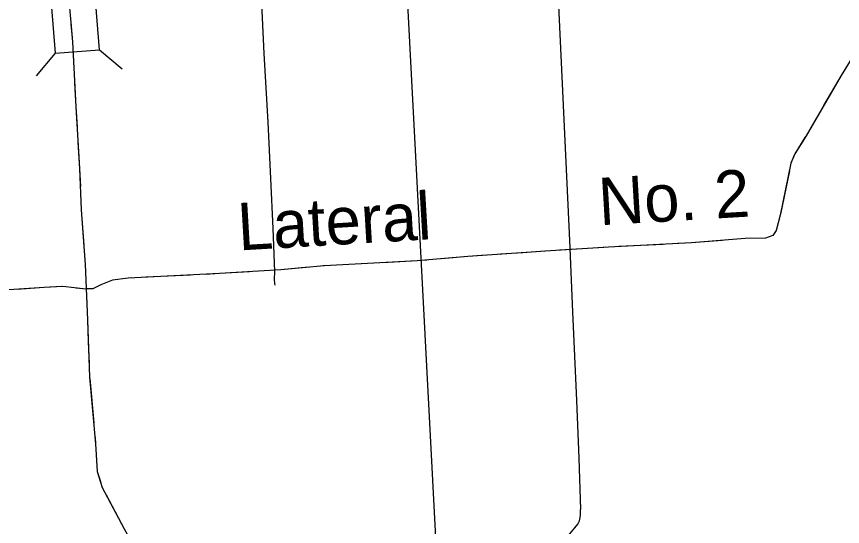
# Model space of a CAD drawing. Extents: x 646058 to 725608, y 1473014 to 1561048.
# Drawn here: x 658973 to 662655, y 1548182 to 1550456 of the extents above; entities that cross this region are included whole.
import ezdxf

# ---------------------------------------------------------------- set-up
doc = ezdxf.new("R2010")
doc.units = 0
doc.layers.add('Default', color=7, linetype='Continuous')

msp = doc.modelspace()

# ---------------------------------------------------------------- linework, layer by layer
at = {"layer": 'Default'}
for p, q in [((659145.5, 1550292.4), (659059.9, 1550191.9)), ((659342.9, 1550308.2), (659443.4, 1550222.6))]:
    msp.add_line(p, q, dxfattribs=at)
msp.add_lwpolyline([(659098, 1550884.5), (659145.5, 1550292.4), (659342.9, 1550308.2), (659295.3, 1550900.3)], close=True, dxfattribs=at)
for points in [[(661378.3, 1550729.1), (661438.2, 1549458.3), (661451.6, 1549139.8), (661469.1, 1548744.2), (661480.1, 1548487), (661487.9, 1548258.1)], [(661378.3, 1550729.1), (661438.2, 1549458.3), (661451.6, 1549139.8), (661469.1, 1548744.2), (661480.1, 1548487), (661487.9, 1548258.1)], [(660846.4, 1548048), (660709.3, 1550682.8)], [(660059.7, 1550642.5), (660076, 1550291.9), (660093.1, 1549984.6)], [(660059.7, 1550642.5), (660076, 1550291.9), (660093.1, 1549984.6)], [(659205.3, 1550547.4), (659215.1, 1550429.5), (659222.5, 1550343.5), (659237.2, 1550053.7), (659254.4, 1549778.6), (659261.8, 1549594.3), (659279, 1549351.2), (659288.8, 1549103.1), (659298.6, 1548847.6), (659325.6, 1548550.4), (659333, 1548427.6), (659355.1, 1548356.4), (659453.3, 1548172.1)], [(659205.3, 1550547.4), (659215.1, 1550429.5), (659222.5, 1550343.5)], [(659215.6, 1550423.5), (659222.5, 1550343.5), (659228.5, 1550225.9)], [(659222.5, 1550343.5), (659237.2, 1550053.7), (659254.4, 1549778.6), (659261.8, 1549594.3), (659279, 1549351.2), (659288.8, 1549103.1), (659298.6, 1548847.6), (659325.6, 1548550.4), (659333, 1548427.6), (659355.1, 1548356.4), (659453.3, 1548172.1)], [(662705.2, 1550284.8), (662649.8, 1550194), (662493, 1549924.9), (662442.3, 1549843.4), (662425.3, 1549801.9), (662377.7, 1549571.3), (662359.2, 1549502.1), (662345.4, 1549480.5), (662311.6, 1549468.2), (662220.9, 1549466.7), (661982.6, 1549446.7), (661612.1, 1549428.2), (661495.2, 1549420.6), (661353.8, 1549411.3), (660984.8, 1549386.7), (660758.8, 1549366.7), (660345.2, 1549345.2), (660151.5, 1549326.8), (659877.9, 1549309.8), (659470.4, 1549289.9), (659401.3, 1549280.6), (659349, 1549260.6), (659313.6, 1549242.2), (659283.3, 1549241.7)], [(662705.2, 1550284.8), (662649.8, 1550194), (662493, 1549924.9), (662442.3, 1549843.4), (662425.3, 1549801.9), (662377.7, 1549571.3), (662359.2, 1549502.1), (662345.4, 1549480.5), (662311.6, 1549468.2), (662220.9, 1549466.7), (661982.6, 1549446.7), (661612.1, 1549428.2), (661495.2, 1549420.6), (661353.8, 1549411.3), (660984.8, 1549386.7), (660758.8, 1549366.7), (660345.2, 1549345.2), (660151.5, 1549326.8), (659877.9, 1549309.8), (659470.4, 1549289.9), (659401.3, 1549280.6), (659349, 1549260.6), (659313.6, 1549242.2), (659283.3, 1549241.7)], [(662671.5, 1550229.7), (662649.8, 1550194), (662571.1, 1550059)], [(659231.8, 1550160), (659237.2, 1550053.7), (659242.9, 1549962.3)], [(660093.1, 1549984.6), (660105.9, 1549734.1), (660115.8, 1549511.8), (660122.6, 1549319.8), (660121.9, 1549283.7), (660122.7, 1549265.3), (660125.1, 1549258)], [(660093.1, 1549984.6), (660105.9, 1549734.1), (660106, 1549730.7)], [(662537.9, 1550002), (662493, 1549924.9), (662487.8, 1549916.6)], [(662487.8, 1549916.6), (662442.3, 1549843.4), (662437.4, 1549831.6)], [(659247, 1549896.5), (659254.4, 1549778.6), (659257.6, 1549698.8)], [(662418.5, 1549768.6), (662378.4, 1549574.7)], [(659260.2, 1549632.8), (659261.8, 1549594.3), (659273, 1549435.3)], [(662361.6, 1549510.9), (662359.2, 1549502.1), (662345.4, 1549480.5), (662311.6, 1549468.2), (662220.9, 1549466.7), (662184.5, 1549463.6)], [(661855.3, 1549440.4), (661657.6, 1549430.5)], [(662118.7, 1549458.1), (661982.6, 1549446.7), (661921.2, 1549443.6)], [(661064.8, 1549392.1), (660984.8, 1549386.7), (660867.5, 1549376.3)], [(661229.5, 1549403), (661130.7, 1549396.5)], [(661328.2, 1549409.6), (661229.5, 1549403)], [(661591.7, 1549426.9), (661495.2, 1549420.6), (661394.1, 1549414)], [(659277.7, 1549369.4), (659279, 1549351.2), (659286.1, 1549171.6)], [(660538.2, 1549355.3), (660345.2, 1549345.2), (660340.5, 1549344.8)], [(660801.7, 1549370.5), (660758.8, 1549366.7), (660604.1, 1549358.7)], [(660011.6, 1549318.1), (659877.9, 1549309.8), (659813.9, 1549306.7)], [(660274.8, 1549338.5), (660151.5, 1549326.8), (660077.5, 1549322.2)], [(659484.3, 1549290.5), (659470.4, 1549289.9), (659401.3, 1549280.6), (659349, 1549260.6), (659313.6, 1549242.2), (659295.2, 1549241.9)], [(659649.1, 1549298.6), (659550.2, 1549293.8)], [(659748, 1549303.5), (659649.1, 1549298.6)], [(658891.1, 1549235.4), (659096.2, 1549249.3), (659180.1, 1549253.8), (659283.3, 1549241.7)], [(658891.1, 1549235.4), (659096.2, 1549249.3), (659180.1, 1549253.8), (659283.3, 1549241.7)], [(658975.6, 1549241.2), (659096.2, 1549249.3), (659173.2, 1549253.4)], [(659238.8, 1549246.9), (659283.3, 1549241.7)], [(659288.7, 1549105.7), (659288.8, 1549103.1), (659292.5, 1549006.7)], [(659292.5, 1549006.7), (659296.3, 1548907.8)], [(659299.1, 1548841.9), (659317.1, 1548644.7)], [(659323, 1548579), (659325.6, 1548550.4), (659333, 1548427.6), (659346.7, 1548383.4)], [(659372.9, 1548323.1), (659453.3, 1548172.1), (659466, 1548148.4)], [(661399.3, 1548081), (661412.6, 1548113.4), (661431.7, 1548140), (661462.4, 1548175.7), (661475.7, 1548192.3), (661483.2, 1548208.1), (661487.4, 1548231.4), (661487.9, 1548258.1)], [(661399.3, 1548081), (661412.6, 1548113.4), (661431.7, 1548140), (661462.4, 1548175.7), (661475.7, 1548192.3), (661483.2, 1548208.1), (661487.4, 1548231.4), (661487.9, 1548258.1)]]:
    msp.add_lwpolyline(points, dxfattribs=at)

# ---------------------------------------------------------------- texts
for s, p in [('No. 2', (661573, 1549525.2)), ('Lateral', (659964.4, 1549413))]:
    msp.add_text(s, height=211.2, rotation=3.3575, dxfattribs=at).set_placement(p)

doc.saveas('drawing.dxf')
